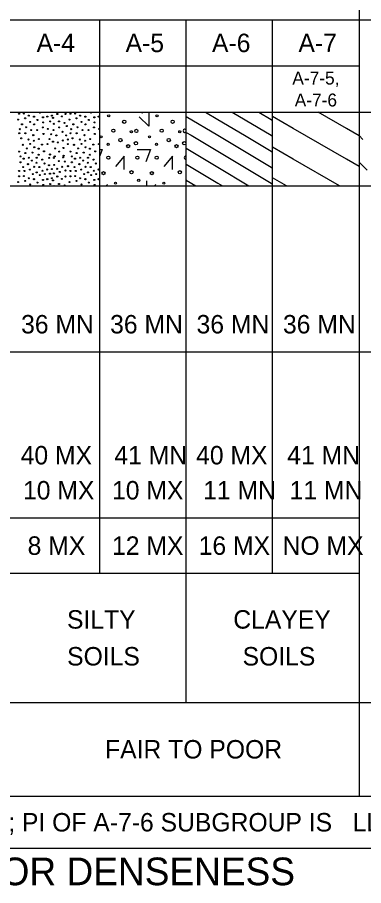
# Model space of a CAD drawing. Extents: x 265553 to 275568, y 168312 to 173522.
# Drawn here: x 267104.8 to 267186.1, y 170744.9 to 170949.1 of the extents above; entities that cross this region are included whole.
import ezdxf

# ---------------------------------------------------------------- set-up
doc = ezdxf.new("R2010")
doc.units = 0
doc.layers.add('Geotech Sheets and Borders Cell', color=7, linetype='Continuous')

msp = doc.modelspace()

# ---------------------------------------------------------------- linework, layer by layer
at = {"layer": 'Geotech Sheets and Borders Cell'}
for p, q in [((267185.03, 170970.22), (267185.03, 170765.99)), ((266920.42, 170948.53), (267297.82, 170948.53)), ((267124.13, 170818.4), (267124.13, 170948.53)), ((267144.43, 170788.03), (267144.43, 170948.53)), ((267164.73, 170818.4), (267164.73, 170948.53)), ((266961.63, 170937.69), (267185.03, 170937.69)), ((266920.42, 170926.84), (267297.82, 170926.84)), ((267149, 170926.84), (267151.85, 170925.13)), ((267155.25, 170926.84), (267164.35, 170921.38)), ((267161.5, 170926.84), (267164.35, 170925.13)), ((267182.09, 170922.99), (267175.43, 170926.84)), ((267144.43, 170925.83), (267151.85, 170921.38)), ((267151.85, 170925.13), (267158.09, 170921.38)), ((267164.35, 170925.13), (267164.73, 170924.9)), ((267169.59, 170922.99), (267164.73, 170925.8)), ((267182.09, 170915.77), (267169.59, 170922.99)), ((267185.03, 170921.29), (267182.09, 170922.99)), ((267144.43, 170922.07), (267145.59, 170921.38)), ((267145.59, 170921.38), (267151.85, 170917.63)), ((267151.85, 170921.38), (267164.35, 170913.88)), ((267158.09, 170921.38), (267164.35, 170917.63)), ((267164.35, 170921.38), (267164.73, 170921.15)), ((267185.95, 170920.42), (267185.03, 170921.33)), ((267144.43, 170918.33), (267151.85, 170913.88)), ((267151.85, 170917.63), (267164.35, 170910.13)), ((267164.35, 170917.63), (267164.73, 170917.4)), ((267169.59, 170915.77), (267164.73, 170918.58)), ((267144.43, 170914.58), (267151.85, 170910.13)), ((267180.47, 170909.49), (267169.59, 170915.77)), ((267185.03, 170914.07), (267182.09, 170915.77)), ((267186.9, 170913.18), (267185.03, 170915.04)), ((267151.85, 170913.88), (267159.17, 170909.49)), ((267164.35, 170913.88), (267164.73, 170913.65)), ((267144.43, 170910.83), (267146.67, 170909.49)), ((267167.97, 170909.49), (267164.73, 170911.36)), ((266920.42, 170909.49), (267297.82, 170909.49)), ((267151.85, 170910.13), (267152.92, 170909.49)), ((267164.35, 170910.13), (267164.73, 170909.9)), ((266920.42, 170870.45), (267297.82, 170870.45)), ((266920.42, 170831.41), (267185.03, 170831.41)), ((266920.42, 170818.4), (267185.03, 170818.4)), ((266920.42, 170788.03), (267297.82, 170788.03)), ((266920.42, 170765.99), (267297.82, 170765.99)), ((267670.42, 170753.71), (266920.42, 170753.71))]:
    msp.add_line(p, q, dxfattribs=at)
for points in [[(267130.18, 170926.66), (267130.18, 170926.84)], [(267141.54, 170926.66), (267141.54, 170926.84)], [(267135.63, 170926.66), (267135.63, 170923.53), (267133.42, 170925.74)], [(267124.13, 170918.08), (267124.68, 170918.08), (267124.13, 170916.57)], [(267132.92, 170918.08), (267136.04, 170918.08), (267134.97, 170915.14)], [(267144.27, 170918.08), (267144.43, 170918.08)], [(267129.85, 170913.32), (267129.85, 170916.44), (267127.83, 170914.05)], [(267141.2, 170913.32), (267141.2, 170916.44), (267139.19, 170914.05)], [(267135.07, 170910.7), (267135.07, 170909.49)], [(267125.62, 170909.49), (267125.92, 170909.79)], [(267136.98, 170909.49), (267137.28, 170909.79)]]:
    msp.add_lwpolyline(points, dxfattribs=at)
for centre, radius in [((267104.95, 170925.09), 0.125), ((267105.18, 170926.46), 0.125), ((267106.31, 170926.51), 0.125), ((267106.6, 170925.38), 0.125), ((267107.45, 170926), 0.125), ((267108.69, 170925.77), 0.125), ((267109.49, 170924.98), 0.125), ((267110.8, 170925.61), 0.125), ((267111.81, 170925.78), 0.125), ((267112.89, 170926), 0.125), ((267113.14, 170925.49), 0.125), ((267114.16, 170926.4), 0.125), ((267115.24, 170925.83), 0.125), ((267116.1, 170926.4), 0.125), ((267117, 170925.09), 0.125), ((267117.23, 170926.46), 0.125), ((267118.36, 170926.51), 0.125), ((267118.65, 170925.38), 0.125), ((267119.5, 170926), 0.125), ((267120.74, 170925.77), 0.125), ((267121.54, 170924.98), 0.125), ((267122.85, 170925.61), 0.125), ((267123.86, 170925.78), 0.125), ((267126.22, 170925.96), 0.25), ((267129.88, 170924.57), 0.375), ((267137.58, 170925.96), 0.25), ((267141.24, 170924.57), 0.375), ((267105.35, 170922.83), 0.125), ((267105.86, 170923.96), 0.125), ((267106.82, 170923.28), 0.125), ((267107.78, 170924.53), 0.125), ((267108.7, 170923.96), 0.125), ((267110.73, 170923.23), 0.125), ((267110.85, 170924.41), 0.125), ((267111.93, 170922.88), 0.125), ((267112.5, 170924.64), 0.125), ((267113.36, 170924.08), 0.125), ((267114.56, 170924.64), 0.125), ((267114.61, 170923.23), 0.125), ((267115.86, 170924.3), 0.125), ((267116.38, 170923.56), 0.125), ((267117.4, 170922.83), 0.125), ((267117.91, 170923.96), 0.125), ((267118.87, 170923.28), 0.125), ((267119.83, 170924.53), 0.125), ((267120.75, 170923.96), 0.125), ((267122.78, 170923.23), 0.125), ((267122.9, 170924.41), 0.125), ((267123.98, 170922.88), 0.125), ((267127.33, 170922.47), 0.375), ((267132.73, 170922.42), 0.375), ((267138.68, 170922.47), 0.375), ((267105.23, 170921.86), 0.125), ((267105.68, 170920.67), 0.125), ((267106.65, 170921.86), 0.125), ((267108.01, 170922.6), 0.125), ((267108.52, 170921.41), 0.125), ((267109.43, 170922.6), 0.125), ((267110.91, 170921.69), 0.125), ((267112.72, 170921.63), 0.125), ((267113.25, 170922.6), 0.125), ((267113.93, 170921.35), 0.125), ((267115.35, 170922.2), 0.125), ((267116.26, 170921.35), 0.125), ((267117.28, 170921.86), 0.125), ((267117.73, 170920.67), 0.125), ((267118.7, 170921.86), 0.125), ((267120.06, 170922.6), 0.125), ((267120.57, 170921.41), 0.125), ((267121.48, 170922.6), 0.125), ((267122.96, 170921.69), 0.125), ((267124.46, 170921.03), 0.25), ((267131.55, 170922.22), 0.25), ((267135.82, 170921.03), 0.25), ((267142.91, 170922.22), 0.25), ((267106.03, 170919.14), 0.125), ((267107.39, 170920.39), 0.125), ((267107.78, 170919.36), 0.125), ((267108.63, 170920.1), 0.125), ((267108.75, 170918.57), 0.125), ((267109.83, 170920.5), 0.125), ((267110.56, 170919.19), 0.125), ((267111.87, 170919.31), 0.125), ((267112.33, 170920.5), 0.125), ((267113.14, 170919.88), 0.125), ((267114.28, 170919.71), 0.125), ((267115.46, 170920.16), 0.125), ((267116.6, 170920.39), 0.125), ((267116.6, 170919.31), 0.125), ((267118.08, 170919.14), 0.125), ((267119.44, 170920.39), 0.125), ((267119.83, 170919.36), 0.125), ((267120.68, 170920.1), 0.125), ((267120.8, 170918.57), 0.125), ((267121.88, 170920.5), 0.125), ((267122.61, 170919.19), 0.125), ((267123.92, 170919.31), 0.125), ((267126.11, 170919.26), 0.25), ((267128.98, 170920.26), 0.375), ((267130.79, 170918.83), 0.375), ((267132.62, 170919.52), 0.375), ((267137.47, 170919.26), 0.25), ((267140.33, 170920.26), 0.375), ((267142.15, 170918.83), 0.375), ((267143.97, 170919.52), 0.375), ((267105.18, 170917.55), 0.125), ((267106.65, 170917.21), 0.125), ((267106.99, 170918.29), 0.125), ((267108.3, 170917.32), 0.125), ((267109.77, 170918.23), 0.125), ((267109.77, 170916.81), 0.125), ((267111.02, 170917.61), 0.125), ((267112.44, 170916.87), 0.125), ((267113.65, 170918.29), 0.125), ((267114.61, 170917.55), 0.125), ((267115.58, 170918.4), 0.125), ((267115.64, 170916.58), 0.125), ((267117.23, 170917.55), 0.125), ((267118.7, 170917.21), 0.125), ((267119.04, 170918.29), 0.125), ((267120.35, 170917.32), 0.125), ((267121.82, 170918.23), 0.125), ((267121.82, 170916.81), 0.125), ((267123.07, 170917.61), 0.125), ((267105.51, 170916.41), 0.125), ((267105.51, 170915.03), 0.125), ((267106.25, 170915.89), 0.125), ((267107.28, 170914.59), 0.125), ((267107.45, 170916.11), 0.125), ((267108.18, 170915.43), 0.125), ((267109.26, 170914.92), 0.125), ((267109.31, 170916.11), 0.125), ((267110.62, 170915.66), 0.125), ((267111.13, 170914.75), 0.125), ((267112.27, 170916.06), 0.125), ((267113.36, 170916.06), 0.125), ((267113.54, 170916.41), 0.125), ((267114.5, 170915.32), 0.125), ((267115.52, 170916.17), 0.125), ((267115.92, 170915.21), 0.125), ((267117.56, 170916.41), 0.125), ((267117.56, 170915.03), 0.125), ((267118.3, 170915.89), 0.125), ((267119.33, 170914.59), 0.125), ((267119.5, 170916.11), 0.125), ((267120.23, 170915.43), 0.125), ((267121.31, 170914.92), 0.125), ((267121.36, 170916.11), 0.125), ((267122.67, 170915.66), 0.125), ((267123.18, 170914.75), 0.125), ((267126.14, 170916.11), 0.375), ((267132.96, 170916.11), 0.375), ((267137.5, 170916.11), 0.375), ((267105.18, 170912.99), 0.125), ((267106.14, 170913.9), 0.125), ((267106.43, 170912.99), 0.125), ((267107.73, 170913.33), 0.125), ((267108.7, 170913.96), 0.125), ((267109.31, 170912.65), 0.125), ((267109.94, 170913.9), 0.125), ((267110.68, 170913.05), 0.125), ((267111.76, 170913.34), 0.125), ((267112.21, 170914.35), 0.125), ((267112.89, 170913.44), 0.125), ((267113.36, 170912.43), 0.125), ((267113.43, 170914.41), 0.125), ((267114.1, 170913.5), 0.125), ((267114.73, 170912.76), 0.125), ((267115.3, 170913.96), 0.125), ((267116.09, 170913.1), 0.125), ((267116.66, 170914.13), 0.125), ((267117.23, 170912.99), 0.125), ((267118.19, 170913.9), 0.125), ((267118.48, 170912.99), 0.125), ((267119.78, 170913.33), 0.125), ((267120.75, 170913.96), 0.125), ((267121.36, 170912.65), 0.125), ((267121.99, 170913.9), 0.125), ((267122.73, 170913.05), 0.125), ((267123.81, 170913.34), 0.125), ((267125, 170912.48), 0.375), ((267131.58, 170912.7), 0.375), ((267136.36, 170912.48), 0.375), ((267142.94, 170912.7), 0.375), ((267104.95, 170910.38), 0.125), ((267105.18, 170911.74), 0.125), ((267106.31, 170911.8), 0.125), ((267106.6, 170910.66), 0.125), ((267107.45, 170911.29), 0.125), ((267108.41, 170912.26), 0.125), ((267108.69, 170911.06), 0.125), ((267110.05, 170912.03), 0.125), ((267110.8, 170910.89), 0.125), ((267111.25, 170912.26), 0.125), ((267111.81, 170911.06), 0.125), ((267112.44, 170912.37), 0.125), ((267112.89, 170911.29), 0.125), ((267113.14, 170910.78), 0.125), ((267114.16, 170911.69), 0.125), ((267115.24, 170911.12), 0.125), ((267116.1, 170911.69), 0.125), ((267117, 170910.38), 0.125), ((267117.23, 170911.74), 0.125), ((267118.36, 170911.8), 0.125), ((267118.65, 170910.66), 0.125), ((267119.5, 170911.29), 0.125), ((267120.46, 170912.26), 0.125), ((267120.74, 170911.06), 0.125), ((267122.1, 170912.03), 0.125), ((267122.85, 170910.89), 0.125), ((267123.3, 170912.26), 0.125), ((267123.86, 170911.06), 0.125), ((267133.27, 170910.8), 0.25), ((267107.78, 170909.81), 0.125), ((267109.49, 170910.27), 0.125), ((267110.85, 170909.7), 0.125), ((267112.5, 170909.93), 0.125), ((267114.56, 170909.93), 0.125), ((267119.83, 170909.81), 0.125), ((267121.54, 170910.27), 0.125), ((267122.9, 170909.7), 0.125), ((267127.81, 170910.12), 0.25), ((267139.17, 170910.12), 0.25)]:
    msp.add_circle(centre, radius, dxfattribs=at)
for centre, radius, start, end in [((267110.05, 170926.74), 0.125, 128.4735, 51.5265), ((267122.1, 170926.74), 0.125, 128.4735, 51.5265), ((267134.09, 170927.07), 0.375, 217.8115, 322.1885), ((267144.08, 170922.42), 0.375, 22.8613, 337.1387), ((267144.32, 170916.11), 0.375, 72.255, 287.745), ((267144.62, 170910.8), 0.25, 140.1592, 219.8408), ((267113.36, 170909.36), 0.125, 79.3017, 100.6983), ((267115.86, 170909.59), 0.125, 305.1764, 234.8236)]:
    msp.add_arc(centre, radius, start, end, dxfattribs=at)

# ---------------------------------------------------------------- texts
for s, height, p in [('A-4', 4.338, (267109.28, 170940.94)), ('A-5', 4.338, (267130.19, 170940.94)), ('A-6', 4.338, (267150.49, 170940.94)), ('A-7', 4.338, (267170.79, 170940.94)), ('A-7-5,', 3.037, (267169.36, 170933.32)), ('A-7-6', 3.037, (267169.92, 170928.16)), ('36 MN', 4.338, (267105.65, 170874.79)), ('36 MN', 4.338, (267126.56, 170874.79)), ('36 MN', 4.338, (267146.86, 170874.79)), ('36 MN', 4.338, (267167.16, 170874.79)), ('40 MX', 4.338, (267105.55, 170843.99)), ('41 MN', 4.338, (267127.56, 170843.99)), ('40 MX', 4.338, (267146.76, 170843.99)), ('41 MN', 4.338, (267168.16, 170843.99)), ('10 MX', 4.338, (267106.1, 170835.75)), ('10 MX', 4.338, (267127.01, 170835.75)), ('11 MN', 4.338, (267148.41, 170835.75)), ('11 MN', 4.338, (267168.71, 170835.75)), ('8 MX', 4.338, (267107.18, 170822.73)), ('12 MX', 4.338, (267127.01, 170822.73)), ('16 MX', 4.338, (267147.36, 170822.73)), ('NO MX', 4.338, (267167.06, 170822.73)), ('SILTY', 4.338, (267116.43, 170805.38)), ('CLAYEY', 4.338, (267155.49, 170805.38)), ('SOILS', 4.338, (267116.46, 170796.71)), ('SOILS', 4.338, (267157.67, 170796.71)), ('FAIR TO POOR', 4.3381, (267125.37, 170774.84)), ('PI OF A-7-5 SUBGROUP IS    LL - 30 ; PI OF A-7-6 SUBGROUP IS   LL - 30', 4.3381, (267003.66, 170757.68)), ('CONSISTENCY OR DENSENESS', 6.507, (267035.57, 170745.04))]:
    msp.add_text(s, height=height, dxfattribs=at).set_placement(p)

doc.saveas('drawing.dxf')
